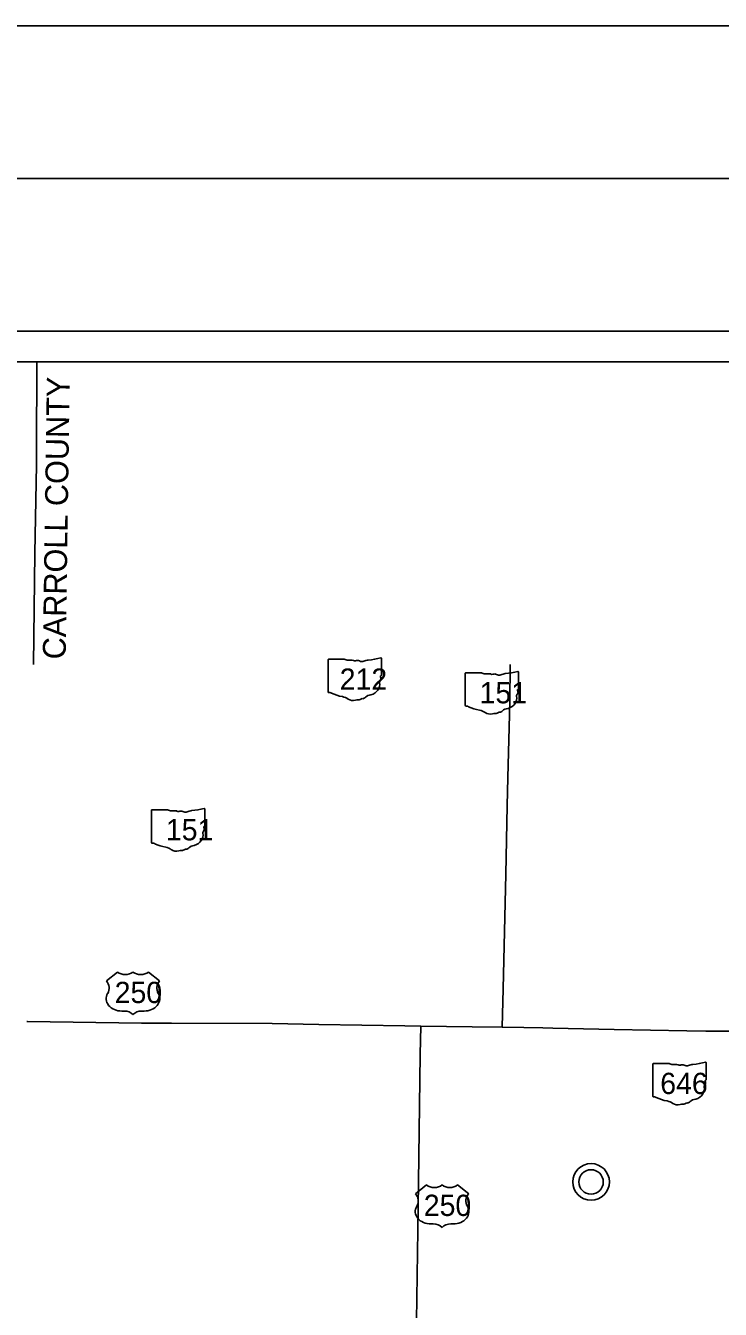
# Model space of a CAD drawing. Extents: x 0 to 34, y -32.5 to 22.
# Drawn here: x 3.115 to 5.387, y 17.798 to 22 of the extents above; entities that cross this region are included whole.
import ezdxf

# ---------------------------------------------------------------- set-up
doc = ezdxf.new("R2010")
doc.units = 0
for name, color, linetype in [('GM_X_Adjacent_County', 7, 'Continuous'), ('GM_X_County', 7, 'Continuous'), ('GM_X_County_Road_Text', 7, 'Continuous'), ('GM_X_County_ROW', 7, 'Continuous'), ('GM_X_Minor_Lake_Text', 7, 'Continuous'), ('GM_X_Minor_River', 7, 'Continuous'), ('GM_X_Minor_River_Text', 7, 'Continuous'), ('GM_X_Section', 7, 'Continuous'), ('GM_X_Township', 7, 'Continuous')]:
    doc.layers.add(name, color=color, linetype=linetype)

msp = doc.modelspace()

# ---------------------------------------------------------------- linework, layer by layer
at = {"layer": 'GM_X_Adjacent_County'}
for radius in [0.06, 0.04]:
    msp.add_circle((4.964, 18.215), radius, dxfattribs=at)
at = {"layer": 'GM_X_County'}
msp.add_lwpolyline([(1.5, 21.5), (33.5, 21.5), (33.5, 0.5), (1.5, 0.5)], close=True, dxfattribs=at)
at = {"layer": 'GM_X_County_Road_Text'}
msp.add_lwpolyline([(3.1515, 20.9), (3.1507, 20.8091), (3.1503, 20.6969), (3.1499, 20.5627), (3.1443, 20.2728), (3.1402, 19.9091)], dxfattribs=at)
at = {"layer": 'GM_X_County_ROW'}
for points in [[(4.6995, 19.9083), (4.6979, 19.7857), (4.6917, 19.5388), (4.6898, 19.4465), (4.685, 19.222), (4.6765, 18.8471), (4.6738, 18.7215)], [(4.4068, 18.7253), (4.3552, 18.7259), (4.0731, 18.7306), (3.921, 18.7334), (3.5921, 18.7345), (3.5409, 18.7345), (3.4931, 18.7351), (3.1202, 18.7405), (3.1184, 18.7405)], [(4.3922, 17.686), (4.3981, 18.1308), (4.405, 18.6324), (4.4068, 18.7253), (4.5752, 18.7229), (4.6738, 18.7215), (4.7436, 18.7202), (4.8067, 18.719), (4.839, 18.7183), (5.0397, 18.7143), (5.277, 18.7096), (5.3393, 18.7088), (5.4404, 18.7084)]]:
    msp.add_lwpolyline(points, dxfattribs=at)
at = {"layer": 'GM_X_Minor_Lake_Text'}
for p, q in [((3.4148, 18.902), (3.3786, 18.873)), ((3.5526, 18.873), (3.5163, 18.902)), ((3.4293, 18.7744), (3.4366, 18.7744)), ((3.4946, 18.7744), (3.5018, 18.7744)), ((4.4259, 18.2051), (4.3897, 18.1761)), ((4.5637, 18.1761), (4.5275, 18.2051)), ((4.4404, 18.0775), (4.4477, 18.0775)), ((4.5057, 18.0775), (4.5129, 18.0775))]:
    msp.add_line(p, q, dxfattribs=at)
for centre, major_axis, start_param, end_param in [((3.337, 18.8497), (0.0508, 0), 5.838949, 6.894067), ((3.4402, 18.9227), (-0.0363, 0), 0.795399, 2.346194), ((3.491, 18.9227), (-0.0363, 0), 0.795399, 2.346194), ((3.5942, 18.8497), (-0.0508, 0), 5.672304, 6.727422), ((3.4288, 18.815), (0.0508, 0), 2.702327, 4.723529), ((3.5024, 18.815), (-0.0508, 0), 1.559657, 3.580859), ((3.4366, 18.7454), (-0.0363, 0), 3.785094, 4.712389), ((3.4946, 18.7454), (-0.0363, 0), 4.712389, 5.639684), ((4.4513, 18.2258), (-0.0363, 0), 0.795399, 2.346194), ((4.5021, 18.2258), (-0.0363, 0), 0.795399, 2.346194), ((4.3481, 18.1528), (0.0508, 0), 5.838949, 6.894067), ((4.6053, 18.1528), (-0.0508, 0), 5.672304, 6.727422), ((4.4399, 18.1181), (0.0508, 0), 2.702327, 4.723529), ((4.5135, 18.1181), (-0.0508, 0), 1.559657, 3.580859), ((4.4477, 18.0485), (-0.0363, 0), 3.785094, 4.712389), ((4.5057, 18.0485), (-0.0363, 0), 4.712389, 5.639684)]:
    msp.add_ellipse(centre, major_axis=major_axis, ratio=0.8, start_param=start_param, end_param=end_param, dxfattribs=at)
at = {"layer": 'GM_X_Minor_River_Text'}
for p, q in [((4.1042, 19.9244), (4.1042, 19.8187)), ((4.1569, 19.9262), (4.1059, 19.9262)), ((4.2783, 19.8736), (4.2783, 19.9288)), ((4.5526, 19.88), (4.5526, 19.7743)), ((4.6053, 19.8818), (4.5543, 19.8818)), ((4.7266, 19.8291), (4.7266, 19.8844)), ((4.2782, 19.8736), (4.2783, 19.8736)), ((4.7266, 19.8291), (4.7266, 19.8291)), ((3.5263, 19.4314), (3.5263, 19.3257)), ((3.579, 19.4332), (3.528, 19.4332)), ((3.7003, 19.3805), (3.7003, 19.4358)), ((3.7003, 19.3806), (3.7003, 19.3805)), ((5.1664, 18.6009), (5.1664, 18.4952)), ((5.2191, 18.6027), (5.1681, 18.6027)), ((5.3404, 18.55), (5.3404, 18.6053)), ((5.3404, 18.5501), (5.3404, 18.55))]:
    msp.add_line(p, q, dxfattribs=at)
for centre, major_axis, start_param, end_param in [((4.1062, 19.9246), (0.00202, 0), 1.712693, 3.28349), ((4.169, 19.9385), (0.0196, 0), 4.042523, 4.731795), ((4.1755, 19.8669), (0.0702, 0), 1.404758, 1.657858), ((4.1915, 19.9252), (0.00564, 0), 3.836095, 5.185415), ((4.1997, 19.913), (0.0117, 0), 0.950623, 2.079405), ((4.2149, 19.9297), (0.0141, 0), 4.081561, 5.145723), ((4.2398, 19.8939), (0.0371, 0), 1.699011, 2.107814), ((4.2163, 20.0703), (0.1845, 0), 4.814394, 5.042369), ((4.2763, 19.9291), (0.00194, 0), 6.141152, 7.989035), ((4.5546, 19.8802), (0.00202, 0), 1.712693, 3.28349), ((4.6174, 19.894), (0.0196, 0), 4.042523, 4.731795), ((4.6239, 19.8225), (0.0702, 0), 1.404758, 1.657858), ((4.6398, 19.8807), (0.00564, 0), 3.836095, 5.185415), ((4.6481, 19.8685), (0.0117, 0), 0.950623, 2.079405), ((4.6632, 19.8853), (0.0141, 0), 4.081561, 5.145723), ((4.6882, 19.8495), (0.0371, 0), 1.699011, 2.107814), ((4.6646, 20.0258), (0.1845, 0), 4.814394, 5.042369), ((4.7247, 19.8846), (0.00194, 0), 6.141152, 7.989035), ((4.2266, 19.8434), (0.0462, 0), 5.101752, 6.440018), ((4.2852, 19.8504), (0.0131, 0), 2.387724, 3.262537), ((4.2778, 19.8695), (0.003, 0), 1.883978, 3.671073), ((4.2587, 19.8625), (0.018, 0), 5.934695, 6.695948), ((4.2762, 19.8733), (0.00207, 0), 5.05454, 6.418171), ((4.1062, 19.8185), (0.00203, 0), 3.00124, 4.508301), ((4.1066, 19.8293), (0.0155, 0), 4.665946, 4.897461), ((4.1097, 19.8126), (0.0056, 0), 0.519207, 1.627899), ((4.1804, 19.9076), (0.1333, 0), 4.195997, 4.488961), ((4.1407, 19.7713), (0.0417, 0), 0.823519, 1.323587), ((4.1858, 19.8121), (0.0265, 0), 4.026481, 4.996735), ((4.201, 19.7756), (0.0217, 0), 1.495662, 1.94098), ((4.203, 19.8042), (0.0141, 0), 4.691044, 5.507374), ((4.2157, 19.794), (0.00397, 0), 1.147584, 2.315152), ((4.214, 19.8085), (0.0149, 0), 4.937069, 5.64225), ((4.2461, 19.7891), (0.0253, 0), 1.647645, 2.488434), ((4.675, 19.799), (0.0462, 0), 5.101752, 6.440018), ((4.7336, 19.806), (0.0131, 0), 2.387724, 3.262537), ((4.7262, 19.8251), (0.003, 0), 1.883978, 3.671073), ((4.7071, 19.8181), (0.018, 0), 5.934695, 6.695948), ((4.7245, 19.8289), (0.00207, 0), 5.05454, 6.418171), ((4.5546, 19.7741), (0.00203, 0), 3.00124, 4.508301), ((4.5549, 19.7849), (0.0155, 0), 4.665946, 4.897461), ((4.5581, 19.7682), (0.0056, 0), 0.519207, 1.627899), ((4.6287, 19.8631), (0.1333, 0), 4.195997, 4.488961), ((4.589, 19.7268), (0.0417, 0), 0.823519, 1.323587), ((4.6341, 19.7677), (0.0265, 0), 4.026481, 4.996735), ((4.6513, 19.7598), (0.0141, 0), 4.691044, 5.507374), ((4.6641, 19.7495), (0.00397, 0), 1.147584, 2.315152), ((4.6624, 19.7641), (0.0149, 0), 4.937069, 5.64225), ((4.6944, 19.7446), (0.0253, 0), 1.647645, 2.488434), ((4.6494, 19.7311), (0.0217, 0), 1.495662, 1.94098), ((3.5283, 19.4316), (0.00202, 0), 1.712693, 3.28349), ((3.5911, 19.4455), (0.0196, 0), 4.042523, 4.731795), ((3.5976, 19.3739), (0.0702, 0), 1.404758, 1.657858), ((3.6135, 19.4321), (0.00564, 0), 3.836095, 5.185415), ((3.6218, 19.4199), (0.0117, 0), 0.950623, 2.079405), ((3.6369, 19.4367), (0.0141, 0), 4.081561, 5.145723), ((3.6619, 19.4009), (0.0371, 0), 1.699011, 2.107814), ((3.6383, 19.5772), (0.1845, 0), 4.814394, 5.042369), ((3.6984, 19.436), (0.00194, 0), 6.141152, 7.989035), ((3.6999, 19.3765), (0.003, 0), 1.883978, 3.671073), ((3.6808, 19.3695), (0.018, 0), 5.934695, 6.695948), ((3.6982, 19.3803), (0.00207, 0), 5.05454, 6.418171), ((3.6487, 19.3504), (0.0462, 0), 5.101752, 6.440018), ((3.7073, 19.3574), (0.0131, 0), 2.387724, 3.262537), ((3.5283, 19.3255), (0.00203, 0), 3.00124, 4.508301), ((3.5286, 19.3363), (0.0155, 0), 4.665946, 4.897461), ((3.5318, 19.3196), (0.0056, 0), 0.519207, 1.627899), ((3.6024, 19.4146), (0.1333, 0), 4.195997, 4.488961), ((3.5627, 19.2782), (0.0417, 0), 0.823519, 1.323587), ((3.6078, 19.3191), (0.0265, 0), 4.026481, 4.996735), ((3.6231, 19.2826), (0.0217, 0), 1.495662, 1.94098), ((3.625, 19.3112), (0.0141, 0), 4.691044, 5.507374), ((3.6378, 19.3009), (0.00397, 0), 1.147584, 2.315152), ((3.6361, 19.3155), (0.0149, 0), 4.937069, 5.64225), ((3.6681, 19.296), (0.0253, 0), 1.647645, 2.488434), ((5.1684, 18.6011), (0.00202, 0), 1.712693, 3.28349), ((5.2312, 18.615), (0.0196, 0), 4.042523, 4.731795), ((5.2377, 18.5434), (0.0702, 0), 1.404758, 1.657858), ((5.2536, 18.6017), (0.00564, 0), 3.836095, 5.185415), ((5.2619, 18.5894), (0.0117, 0), 0.950623, 2.079405), ((5.277, 18.6062), (0.0141, 0), 4.081561, 5.145723), ((5.302, 18.5704), (0.0371, 0), 1.699011, 2.107814), ((5.2784, 18.7468), (0.1845, 0), 4.814394, 5.042369), ((5.3385, 18.6055), (0.00194, 0), 6.141152, 7.989035), ((5.3473, 18.5269), (0.0131, 0), 2.387724, 3.262537), ((5.34, 18.546), (0.003, 0), 1.883978, 3.671073), ((5.3209, 18.539), (0.018, 0), 5.934695, 6.695948), ((5.3383, 18.5498), (0.00207, 0), 5.05454, 6.418171), ((5.1684, 18.495), (0.00203, 0), 3.00124, 4.508301), ((5.1687, 18.5058), (0.0155, 0), 4.665946, 4.897461), ((5.1719, 18.4891), (0.0056, 0), 0.519207, 1.627899), ((5.2425, 18.5841), (0.1333, 0), 4.195997, 4.488961), ((5.2888, 18.5199), (0.0462, 0), 5.101752, 6.440018), ((5.2028, 18.4477), (0.0417, 0), 0.823519, 1.323587), ((5.2479, 18.4886), (0.0265, 0), 4.026481, 4.996735), ((5.2632, 18.4521), (0.0217, 0), 1.495662, 1.94098), ((5.2651, 18.4807), (0.0141, 0), 4.691044, 5.507374), ((5.2779, 18.4704), (0.00397, 0), 1.147584, 2.315152), ((5.2762, 18.485), (0.0149, 0), 4.937069, 5.64225), ((5.3082, 18.4655), (0.0253, 0), 1.647645, 2.488434)]:
    msp.add_ellipse(centre, major_axis=major_axis, ratio=0.8, start_param=start_param, end_param=end_param, dxfattribs=at)
at = {"layer": 'GM_X_Section'}
msp.add_lwpolyline([(0, 0), (34, 0), (34, 22), (0, 22)], close=True, dxfattribs=at)
at = {"layer": 'GM_X_Township'}
for p, q in [((2, 21), (9, 21)), ((2.1, 20.9), (8.9, 20.9))]:
    msp.add_line(p, q, dxfattribs=at)

# ---------------------------------------------------------------- texts
at = {"layer": 'GM_X_Minor_Lake_Text'}
for p in [(3.4057, 18.8005), (4.4169, 18.1036)]:
    msp.add_text('250', height=0.06961, dxfattribs=at).set_placement(p)
at = {"layer": 'GM_X_Minor_River'}
msp.add_text('CARROLL COUNTY', height=0.075, rotation=89.1612, dxfattribs=at).set_placement((3.2454, 19.9253))
at = {"layer": 'GM_X_Minor_River_Text'}
for s, p in [('212', (4.1418, 19.8262)), ('151', (4.5995, 19.7817)), ('151', (3.5732, 19.3332)), ('646', (5.1904, 18.5027))]:
    msp.add_text(s, height=0.06961, dxfattribs=at).set_placement(p)

doc.saveas('drawing.dxf')
